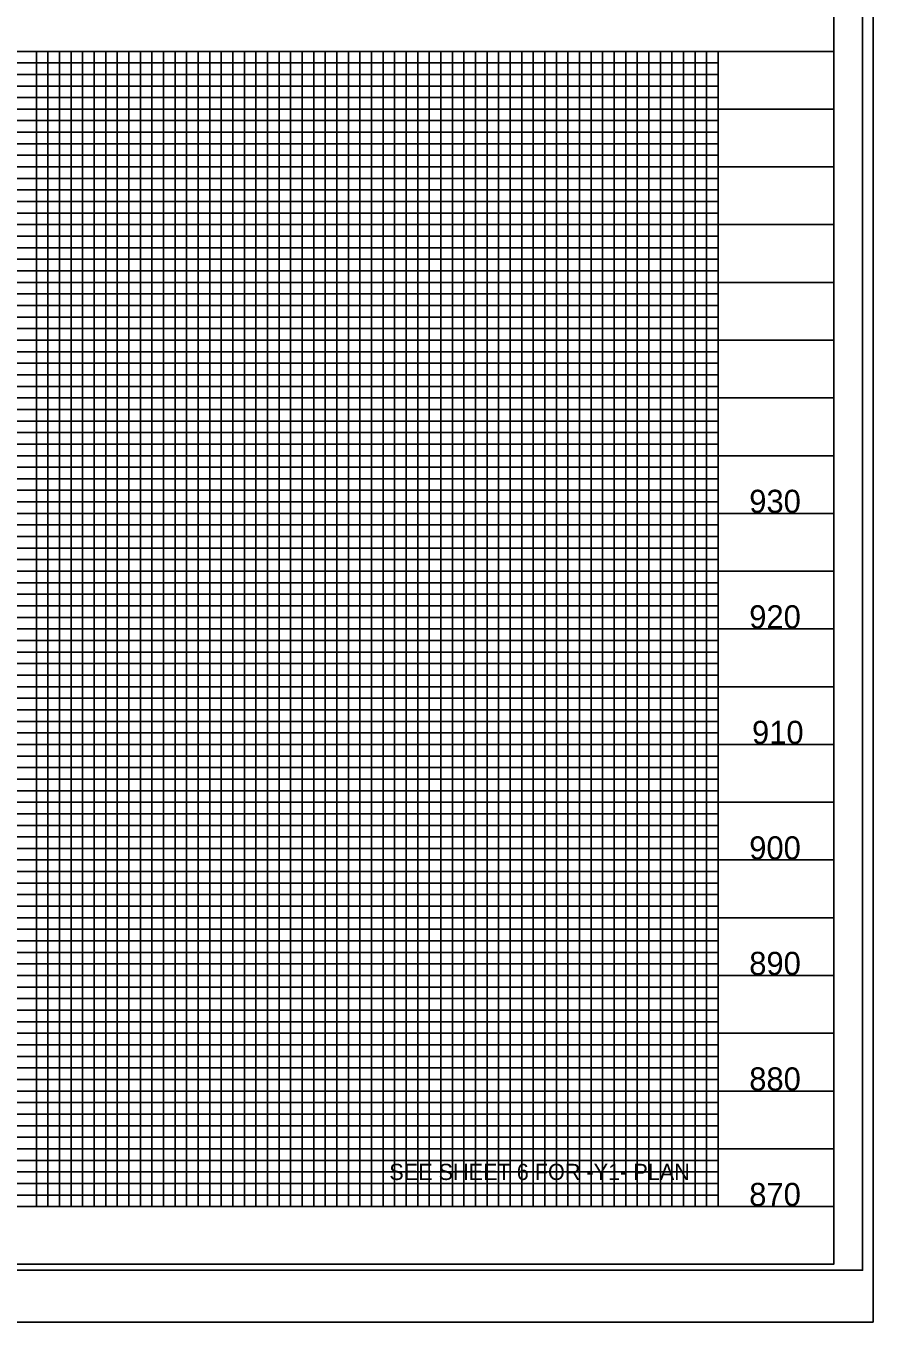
# Model space of a CAD drawing. Extents: x 1648157 to 1650776, y 832691 to 834781.
# Drawn here: x 1650180 to 1650546, y 832691 to 833252 of the extents above; entities that cross this region are included whole.
import ezdxf

# ---------------------------------------------------------------- set-up
doc = ezdxf.new("R2010")
doc.units = 0
for name, color, linetype in [('Exist Vertical Profile Vertical Axis Label', 7, 'Continuous'), ('Prop Dimension', 7, 'Continuous'), ('Prop Grid Mask', 7, 'Continuous'), ('Sheet Cutting Line CELL', 7, 'Continuous'), ('Sheet DOT Grid CELL', 7, 'Continuous'), ('Sheet Layout Profile Border Port 2', 7, 'Continuous'), ('Sheet Plot Border Inside CELL', 7, 'Continuous'), ('Sheet Plot Border Outside CELL', 7, 'Continuous'), ('Sheet Profile CELL', 7, 'Continuous'), ('Sheet Profile Grid Major CELL', 7, 'Continuous'), ('Sheet Profile Grid Middle CELL', 7, 'Continuous'), ('Sheet Profile Grid Minor CELL', 7, 'Continuous')]:
    doc.layers.add(name, color=color, linetype=linetype)

msp = doc.modelspace()

# ---------------------------------------------------------------- linework, layer by layer
at = {"layer": 'Prop Grid Mask'}
msp.add_lwpolyline([(1650334.28, 832766.02), (1650334.28, 832746.02), (1650469.28, 832746.02), (1650469.28, 832766.02)], close=True, dxfattribs=at)
at = {"layer": 'Sheet Cutting Line CELL'}
msp.add_line((1648862.28, 832691.02), (1650546.28, 832691.02), dxfattribs=at)
at = {"layer": 'Sheet DOT Grid CELL'}
for p, q in [((1649029.28, 833241.02), (1650529.17, 833241.02)), ((1650229.28, 833241.02), (1650229.28, 832741.02)), ((1650279.28, 833241.02), (1650279.28, 832741.02)), ((1650329.28, 833241.02), (1650329.28, 832741.02)), ((1650379.28, 833241.02), (1650379.28, 832741.02)), ((1650429.28, 833241.02), (1650429.28, 832741.02)), ((1650479.28, 833241.02), (1650479.28, 832741.02)), ((1649029.28, 833191.02), (1650529.17, 833191.02)), ((1649029.28, 833141.02), (1650529.17, 833141.02)), ((1649029.28, 833091.02), (1650529.17, 833091.02)), ((1649029.28, 833041.02), (1650529.17, 833041.02)), ((1649029.28, 832991.02), (1650529.17, 832991.02)), ((1649029.28, 832941.02), (1650529.17, 832941.02)), ((1649029.28, 832891.02), (1650529.17, 832891.02)), ((1649029.28, 832841.02), (1650529.17, 832841.02)), ((1649029.28, 832791.02), (1650529.17, 832791.02))]:
    msp.add_line(p, q, dxfattribs=at)
at = {"layer": 'Sheet Layout Profile Border Port 2'}
msp.add_lwpolyline([(1649079.28, 833241.02), (1650479.28, 833241.02), (1650479.28, 832741.02), (1649079.28, 832741.02)], close=True, dxfattribs=at)
at = {"layer": 'Sheet Plot Border Inside CELL'}
msp.add_lwpolyline([(1648875.28, 832713.47), (1650541.78, 832713.47), (1650541.78, 833768.57), (1648875.28, 833768.57)], close=True, dxfattribs=at)
at = {"layer": 'Sheet Plot Border Outside CELL'}
msp.add_lwpolyline([(1648862.28, 832691.02), (1650546.28, 832691.02), (1650546.28, 833791.02), (1648862.28, 833791.02)], close=True, dxfattribs=at)
at = {"layer": 'Sheet Profile CELL'}
for p, q in [((1649029.28, 833241.02), (1650529.28, 833241.02)), ((1650529.28, 832741.02), (1649029.28, 832741.02)), ((1649029.28, 832716.02), (1650529.28, 832716.02))]:
    msp.add_line(p, q, dxfattribs=at)
msp.add_lwpolyline([(1650529.28, 833766.02), (1649029.28, 833766.02), (1649029.28, 832716.02), (1650529.28, 832716.02)], close=True, dxfattribs=at)
at = {"layer": 'Sheet Profile Grid Major CELL'}
for p, q in [((1650229.28, 833241.02), (1650279.28, 833241.02)), ((1650329.28, 833241.02), (1650379.28, 833241.02)), ((1650429.28, 833241.02), (1650479.28, 833241.02)), ((1650429.28, 832741.02), (1650429.28, 832741.02))]:
    msp.add_line(p, q, dxfattribs=at)
for points in [[(1650179.28, 832741.02), (1650229.28, 832741.02), (1650229.28, 833241.02), (1650279.28, 833241.02), (1650279.28, 832741.02), (1650329.28, 832741.02), (1650329.28, 833241.02), (1650379.28, 833241.02), (1650379.28, 832741.02), (1650429.28, 832741.02), (1650429.28, 832741.02), (1650429.28, 833241.02), (1650479.28, 833241.02), (1650479.28, 832741.02)], [(1650529.28, 833191.02), (1649029.28, 833191.02)], [(1650529.28, 833141.02), (1649029.28, 833141.02), (1649029.28, 833091.02), (1650529.28, 833091.02)], [(1650529.28, 833041.02), (1649029.28, 833041.02), (1649029.28, 832991.02), (1650529.28, 832991.02)], [(1650529.28, 832941.02), (1649029.28, 832941.02), (1649029.28, 832891.02), (1650529.28, 832891.02)], [(1650529.28, 832841.02), (1649029.28, 832841.02), (1649029.28, 832841.02), (1649029.28, 832791.02), (1650529.28, 832791.02)], [(1650529.28, 832741.02), (1649029.28, 832741.02)]]:
    msp.add_lwpolyline(points, dxfattribs=at)
at = {"layer": 'Sheet Profile Grid Middle CELL'}
for points in [[(1650154.28, 833241.02), (1650204.28, 833241.02), (1650204.28, 832741.02), (1650254.28, 832741.02), (1650254.28, 833241.02), (1650304.28, 833241.02), (1650304.28, 832741.02), (1650354.28, 832741.02), (1650354.28, 833241.02), (1650404.28, 833241.02), (1650404.28, 832741.02), (1650454.28, 832741.02), (1650454.28, 833241.02)], [(1649029.28, 833216.02), (1650529.28, 833216.02)], [(1650529.28, 833166.02), (1649029.28, 833166.02), (1649029.28, 833116.02), (1650529.28, 833116.02)], [(1650529.28, 833066.02), (1649029.28, 833066.02), (1649029.28, 833016.02), (1650529.28, 833016.02)], [(1650529.28, 832966.02), (1649029.28, 832966.02), (1649029.28, 832916.02), (1650529.28, 832916.02)], [(1650529.28, 832866.02), (1649029.28, 832866.02), (1649029.28, 832816.02), (1650529.28, 832816.02)], [(1650529.28, 832766.02), (1649029.28, 832766.02)]]:
    msp.add_lwpolyline(points, dxfattribs=at)
at = {"layer": 'Sheet Profile Grid Minor CELL'}
for p, q in [((1649079.28, 833236.02), (1650479.28, 833236.02)), ((1650479.28, 833231.02), (1649079.28, 833231.02)), ((1649079.28, 833226.02), (1650479.28, 833226.02)), ((1650479.28, 833221.02), (1649079.28, 833221.02)), ((1649079.28, 833211.02), (1650479.28, 833211.02)), ((1650479.28, 833206.02), (1649079.28, 833206.02)), ((1649079.28, 833201.02), (1650479.28, 833201.02)), ((1650479.28, 833196.02), (1649079.28, 833196.02)), ((1649079.28, 833186.02), (1650479.28, 833186.02)), ((1650479.28, 833181.02), (1649079.28, 833181.02)), ((1649079.28, 833176.02), (1650479.28, 833176.02)), ((1650479.28, 833171.02), (1649079.28, 833171.02)), ((1649079.28, 833161.02), (1650479.28, 833161.02)), ((1650479.28, 833156.02), (1649079.28, 833156.02)), ((1649079.28, 833151.02), (1650479.28, 833151.02)), ((1650479.28, 833146.02), (1649079.28, 833146.02)), ((1649079.28, 833136.02), (1650479.28, 833136.02)), ((1650479.28, 833131.02), (1649079.28, 833131.02)), ((1649079.28, 833126.02), (1650479.28, 833126.02)), ((1650479.28, 833121.02), (1649079.28, 833121.02)), ((1649079.28, 833111.02), (1650479.28, 833111.02)), ((1650479.28, 833106.02), (1649079.28, 833106.02)), ((1649079.28, 833101.02), (1650479.28, 833101.02)), ((1650479.28, 833096.02), (1649079.28, 833096.02)), ((1649079.28, 833086.02), (1650479.28, 833086.02)), ((1650479.28, 833081.02), (1649079.28, 833081.02)), ((1649079.28, 833076.02), (1650479.28, 833076.02)), ((1650479.28, 833071.02), (1649079.28, 833071.02)), ((1649079.28, 833061.02), (1650479.28, 833061.02)), ((1650479.28, 833056.02), (1649079.28, 833056.02)), ((1649079.28, 833051.02), (1650479.28, 833051.02)), ((1650479.28, 833046.02), (1649079.28, 833046.17)), ((1649079.28, 833036.02), (1650479.28, 833036.02)), ((1650479.28, 833031.02), (1649079.28, 833031.02)), ((1649079.28, 833026.02), (1650479.28, 833026.02)), ((1650479.28, 833021.02), (1649079.28, 833021.02)), ((1649079.28, 833011.02), (1650479.28, 833011.02)), ((1650479.28, 833006.02), (1649079.28, 833006.02)), ((1649079.28, 833001.02), (1650479.28, 833001.02)), ((1650479.28, 832996.02), (1649079.28, 832996.02)), ((1649079.28, 832986.02), (1650479.28, 832986.02)), ((1650479.28, 832981.02), (1649079.28, 832981.02)), ((1649079.28, 832976.02), (1650479.28, 832976.02)), ((1650479.28, 832971.02), (1649079.28, 832971.02)), ((1649079.28, 832961.02), (1650479.28, 832961.02)), ((1650479.28, 832956.02), (1649079.28, 832956.02)), ((1649079.28, 832951.02), (1650479.28, 832951.02)), ((1650479.28, 832946.02), (1649079.28, 832946.02)), ((1649079.28, 832936.02), (1650479.28, 832936.02)), ((1650479.28, 832931.02), (1649079.28, 832931.02)), ((1649079.28, 832926.02), (1650479.28, 832926.02)), ((1650479.28, 832921.02), (1649079.28, 832921.02)), ((1649079.28, 832911.02), (1650479.28, 832911.02)), ((1650479.28, 832906.02), (1649079.28, 832906.02)), ((1649079.28, 832901.02), (1650479.28, 832901.02)), ((1650479.28, 832896.02), (1649079.28, 832896.02)), ((1649079.28, 832886.02), (1650479.28, 832886.02)), ((1650479.28, 832881.02), (1649079.28, 832881.02)), ((1649079.28, 832876.02), (1650479.28, 832876.02)), ((1650479.28, 832871.02), (1649079.28, 832871.02)), ((1649079.28, 832861.02), (1650479.28, 832861.02)), ((1650479.28, 832856.02), (1649079.28, 832856.02)), ((1649079.28, 832851.02), (1650479.28, 832851.02)), ((1650479.28, 832846.02), (1649079.28, 832846.02)), ((1649079.28, 832836.02), (1650479.28, 832836.02)), ((1650479.28, 832831.02), (1649079.28, 832831.02)), ((1649079.28, 832826.02), (1650479.28, 832826.02)), ((1650479.28, 832821.02), (1649079.28, 832821.02)), ((1649079.28, 832811.02), (1650479.28, 832811.02)), ((1650479.28, 832806.02), (1649079.28, 832806.02)), ((1649079.28, 832801.02), (1650479.28, 832801.02)), ((1650479.28, 832796.02), (1649079.28, 832796.02)), ((1649079.28, 832786.02), (1650479.28, 832786.02)), ((1650479.28, 832781.02), (1649079.28, 832781.02)), ((1649079.28, 832776.02), (1650479.28, 832776.02)), ((1650479.28, 832771.02), (1649079.28, 832771.02)), ((1649079.28, 832761.02), (1650479.28, 832761.02)), ((1650479.28, 832756.02), (1649079.28, 832756.02)), ((1649079.28, 832751.02), (1650479.28, 832751.02)), ((1649079.28, 832746.02), (1650479.28, 832746.02)), ((1650479.28, 832746.02), (1650479.28, 832746.02))]:
    msp.add_line(p, q, dxfattribs=at)
for points in [[(1650174.28, 833241.02), (1650184.28, 833241.02), (1650184.28, 832741.02), (1650189.28, 832741.02), (1650189.28, 833241.02), (1650194.28, 833241.02), (1650194.28, 832741.02), (1650199.28, 832741.02), (1650199.28, 833241.02), (1650209.28, 833241.02), (1650209.28, 832741.02), (1650214.28, 832741.02), (1650214.28, 833241.02), (1650219.28, 833241.02), (1650219.28, 832741.02)], [(1650219.28, 832741.02), (1650224.28, 832741.02), (1650224.28, 833241.02), (1650234.28, 833241.02), (1650234.28, 832741.02), (1650239.28, 832741.02), (1650239.28, 833241.02), (1650244.28, 833241.02), (1650244.28, 832741.02), (1650249.28, 832741.02), (1650249.28, 833241.02), (1650259.28, 833241.02), (1650259.28, 832741.02), (1650264.28, 832741.02), (1650264.28, 833241.02), (1650269.28, 833241.02), (1650269.28, 832741.02), (1650274.28, 832741.02), (1650274.28, 833241.02), (1650284.28, 833241.02), (1650284.28, 832741.02), (1650289.28, 832741.02), (1650289.28, 833241.02), (1650294.28, 833241.02), (1650294.28, 832741.02), (1650299.28, 832741.02), (1650299.28, 833241.02), (1650309.28, 833241.02), (1650309.28, 832741.02), (1650314.28, 832741.02), (1650314.28, 833241.02), (1650319.28, 833241.02), (1650319.28, 832741.02), (1650324.28, 832741.02), (1650324.28, 833241.02), (1650334.28, 833241.02), (1650334.28, 832741.02), (1650339.28, 832741.02), (1650339.28, 833241.02), (1650344.28, 833241.02), (1650344.28, 832741.02), (1650349.28, 832741.02), (1650349.28, 833241.02), (1650359.28, 833241.02), (1650359.28, 832741.02), (1650364.28, 832741.02), (1650364.28, 833241.02), (1650369.28, 833241.02), (1650369.28, 832741.02), (1650374.28, 832741.02), (1650374.28, 833241.02), (1650384.28, 833241.02), (1650384.28, 832741.02), (1650389.28, 832741.02), (1650389.28, 833241.02), (1650394.28, 833241.02), (1650394.28, 832741.02), (1650399.28, 832741.02), (1650399.28, 833241.02), (1650409.28, 833241.02), (1650409.28, 832741.02), (1650414.28, 832741.02), (1650414.28, 833241.02), (1650419.28, 833241.02), (1650419.28, 832741.02), (1650424.28, 832741.02), (1650424.28, 833241.02), (1650434.28, 833241.02), (1650434.28, 832741.02), (1650439.28, 832741.02), (1650439.28, 833241.02), (1650444.28, 833241.02), (1650444.28, 832741.02), (1650449.28, 832741.02), (1650449.28, 833241.02), (1650459.28, 833241.02), (1650459.28, 832741.02), (1650464.28, 832741.02), (1650464.28, 833241.02), (1650469.28, 833241.02), (1650469.28, 832741.02), (1650474.28, 832741.02), (1650474.28, 833241.02), (1650479.28, 833241.02)]]:
    msp.add_lwpolyline(points, dxfattribs=at)

# ---------------------------------------------------------------- texts
at = {"layer": 'Exist Vertical Profile Vertical Axis Label'}
for s, p in [('930', (1650492.71, 833041.27)), ('920', (1650492.71, 832991.27)), ('910', (1650493.91, 832941.27)), ('900', (1650492.71, 832891.27)), ('890', (1650492.71, 832841.27)), ('880', (1650492.71, 832791.27)), ('870', (1650492.71, 832741.27))]:
    msp.add_text(s, height=10, dxfattribs=at).set_placement(p)
at = {"layer": 'Prop Dimension'}
msp.add_text('SEE SHEET 6 FOR -Y1- PLAN', height=7, dxfattribs=at).set_placement((1650336.97, 832752.52))

doc.saveas('drawing.dxf')
